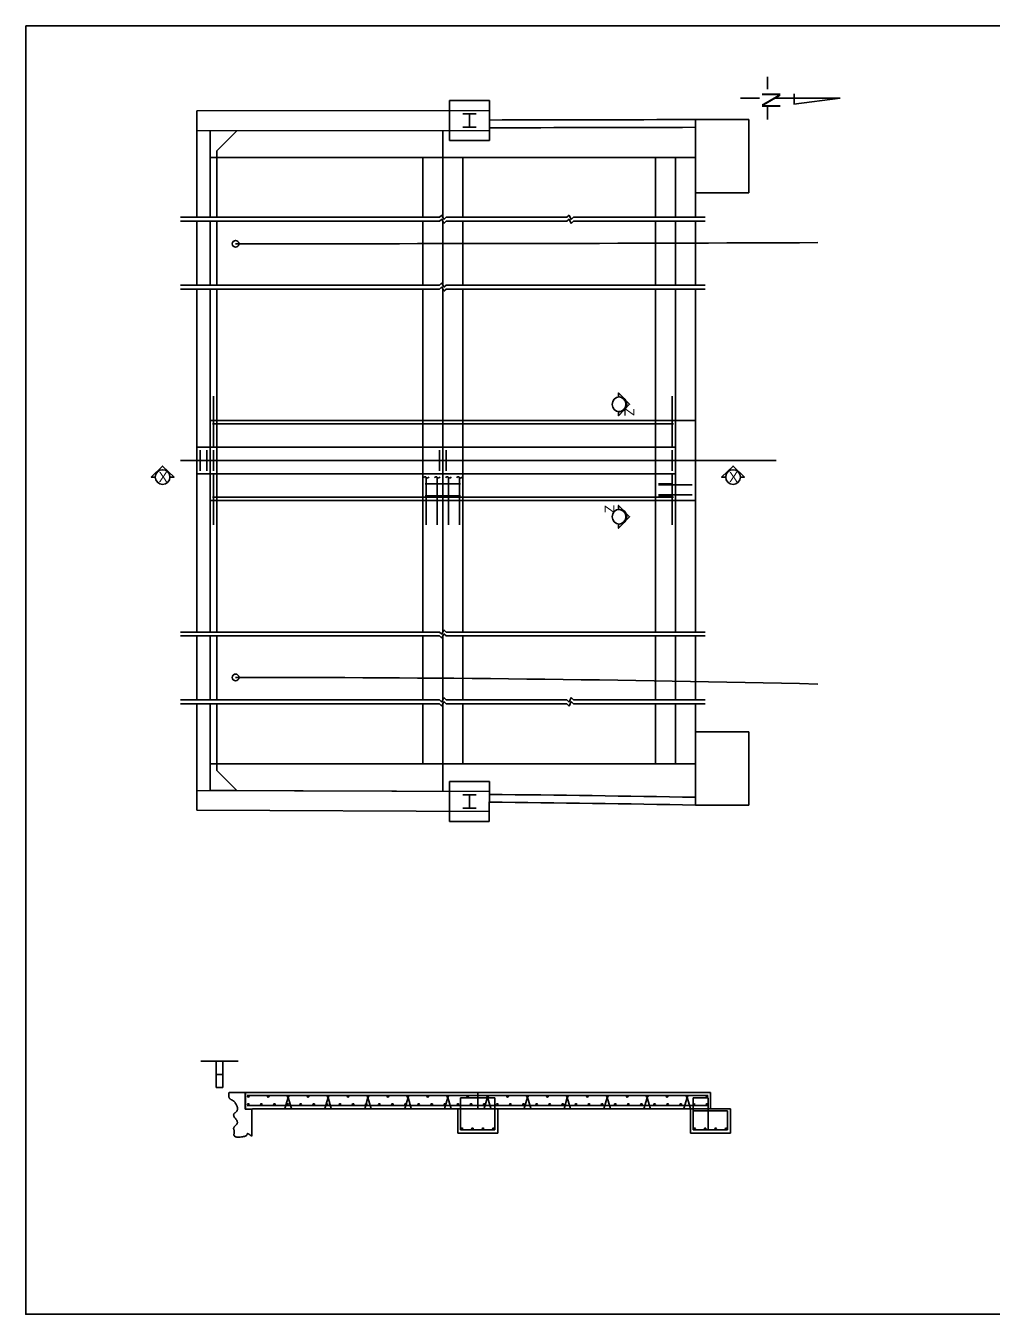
# Model space of a CAD drawing. Extents: x 1531 to 2925, y 1224 to 1658.
# Drawn here: x 2196.7 to 2269.3, y 1331.8 to 1428.7 of the extents above; entities that cross this region are included whole.
import ezdxf

# ---------------------------------------------------------------- set-up
doc = ezdxf.new("R2010")
doc.units = 0
for name, color, linetype in [('B_Border', 7, 'Continuous'), ('BD-EXIST-COSS', 7, 'Continuous'), ('BD-PROP-COSS', 7, 'Continuous'), ('BD-PROP-OSB', 7, 'Continuous'), ('D_FEMA A', 7, 'Continuous'), ('R_Border Prem', 7, 'Continuous'), ('R_Draft', 7, 'Continuous'), ('R_Guard Rail', 7, 'Continuous'), ('R_MOT', 7, 'Continuous'), ('R_Road Edge of Shoulder', 7, 'Continuous'), ('R_ROW Annot', 7, 'Continuous'), ('R_ROW_COA', 7, 'Continuous'), ('R_Survey Control', 7, 'Continuous'), ('R_Wall', 7, 'Continuous')]:
    doc.layers.add(name, color=color, linetype=linetype)

msp = doc.modelspace()

# ---------------------------------------------------------------- linework, layer by layer
at = {"layer": 'B_Border'}
msp.add_line((2208.361, 1396.032), (2253.154, 1396.032), dxfattribs=at)
at = {"layer": 'BD-EXIST-COSS'}
for p, q in [((2210.833, 1400.865), (2210.833, 1397.032)), ((2245.333, 1400.865), (2245.333, 1397.032)), ((2210.75, 1398.782), (2245.417, 1398.782)), ((2209.833, 1396.813), (2209.833, 1395.251)), ((2210.333, 1396.813), (2210.333, 1395.251)), ((2210.833, 1396.813), (2210.833, 1395.251)), ((2227.833, 1396.813), (2227.833, 1395.251)), ((2228.333, 1396.813), (2228.333, 1395.251)), ((2245.333, 1396.813), (2245.333, 1395.251)), ((2210.833, 1395.032), (2210.833, 1391.199)), ((2226.833, 1394.767), (2226.833, 1391.199)), ((2227.667, 1394.767), (2227.667, 1391.199)), ((2228.5, 1394.767), (2228.5, 1391.199)), ((2229.333, 1394.767), (2229.333, 1391.199)), ((2245.333, 1395.032), (2245.333, 1391.199)), ((2226.75, 1394.282), (2229.417, 1394.282)), ((2226.75, 1393.382), (2229.417, 1393.382)), ((2244.292, 1394.282), (2245.375, 1394.282)), ((2244.292, 1394.199), (2246.833, 1394.199)), ((2244.292, 1393.466), (2246.833, 1393.466)), ((2244.292, 1393.382), (2245.375, 1393.382)), ((2210.75, 1393.282), (2245.417, 1393.282)), ((2213.373, 1348.288), (2248.039, 1348.288)), ((2229.414, 1348.108), (2231.998, 1348.108)), ((2229.414, 1348.108), (2229.414, 1345.705)), ((2231.998, 1348.108), (2231.998, 1345.705)), ((2246.914, 1348.108), (2248.025, 1348.108)), ((2246.914, 1348.108), (2246.914, 1345.702)), ((2248.025, 1348.108), (2248.025, 1345.702)), ((2213.373, 1347.538), (2248.039, 1347.538)), ((2246.914, 1347.121), (2249.498, 1347.121)), ((2249.498, 1347.121), (2249.498, 1345.705)), ((2229.414, 1345.705), (2231.998, 1345.705)), ((2246.914, 1345.705), (2249.498, 1345.705))]:
    msp.add_line(p, q, dxfattribs=at)
for centre, radius in [((2213.449, 1348.225), 0.063), ((2214.949, 1348.225), 0.063), ((2216.449, 1348.225), 0.063), ((2217.949, 1348.225), 0.063), ((2219.449, 1348.225), 0.063), ((2220.949, 1348.225), 0.063), ((2222.449, 1348.225), 0.063), ((2223.949, 1348.225), 0.063), ((2225.449, 1348.225), 0.063), ((2226.949, 1348.225), 0.063), ((2228.449, 1348.225), 0.063), ((2229.949, 1348.225), 0.063), ((2231.449, 1348.225), 0.063), ((2232.949, 1348.225), 0.063), ((2234.449, 1348.225), 0.063), ((2235.949, 1348.225), 0.063), ((2237.449, 1348.225), 0.063), ((2238.949, 1348.225), 0.063), ((2240.449, 1348.225), 0.063), ((2241.949, 1348.225), 0.063), ((2243.449, 1348.225), 0.063), ((2244.949, 1348.225), 0.063), ((2246.449, 1348.225), 0.063), ((2247.949, 1348.225), 0.063), ((2213.449, 1347.601), 0.063), ((2214.435, 1347.601), 0.063), ((2215.421, 1347.601), 0.063), ((2216.406, 1347.601), 0.063), ((2217.392, 1347.601), 0.063), ((2218.378, 1347.601), 0.063), ((2219.363, 1347.601), 0.063), ((2220.349, 1347.601), 0.063), ((2221.335, 1347.601), 0.063), ((2222.321, 1347.601), 0.063), ((2223.306, 1347.601), 0.063), ((2224.292, 1347.601), 0.063), ((2225.278, 1347.601), 0.063), ((2226.263, 1347.601), 0.063), ((2227.249, 1347.601), 0.063), ((2228.235, 1347.601), 0.063), ((2229.22, 1347.601), 0.063), ((2230.206, 1347.601), 0.063), ((2231.192, 1347.601), 0.063), ((2232.178, 1347.601), 0.063), ((2233.163, 1347.601), 0.063), ((2234.149, 1347.601), 0.063), ((2235.135, 1347.601), 0.063), ((2236.12, 1347.601), 0.063), ((2237.106, 1347.601), 0.063), ((2238.092, 1347.601), 0.063), ((2239.078, 1347.601), 0.063), ((2240.063, 1347.601), 0.063), ((2241.049, 1347.601), 0.063), ((2242.035, 1347.601), 0.063), ((2243.02, 1347.601), 0.063), ((2244.006, 1347.601), 0.063), ((2244.992, 1347.601), 0.063), ((2245.978, 1347.601), 0.063), ((2246.963, 1347.601), 0.063), ((2247.949, 1347.601), 0.063), ((2229.522, 1345.77), 0.0625), ((2230.311, 1345.77), 0.0625), ((2231.101, 1345.77), 0.0625), ((2231.89, 1345.77), 0.0625), ((2247.022, 1345.77), 0.0625), ((2247.811, 1345.77), 0.0625), ((2248.601, 1345.77), 0.0625), ((2249.39, 1345.77), 0.0625)]:
    msp.add_circle(centre, radius, dxfattribs=at)
for centre, start, end in [((2226.741, 1394.713), 30.26081, 174.78761), ((2226.926, 1394.821), 210.26064, 354.78668), ((2227.574, 1394.713), 30.26081, 174.78761), ((2227.759, 1394.821), 210.26064, 354.78668), ((2228.407, 1394.713), 30.26081, 174.78761), ((2228.593, 1394.821), 210.26064, 354.78668), ((2229.241, 1394.713), 30.26081, 174.78761), ((2229.426, 1394.821), 210.26064, 354.78668)]:
    msp.add_arc(centre, 0.107, start, end, dxfattribs=at)
at = {"layer": 'BD-PROP-COSS'}
for p, q in [((2211.037, 1350.873), (2211.537, 1350.873)), ((2213.248, 1348.496), (2213.206, 1348.496)), ((2230.706, 1348.496), (2230.706, 1347.288))]:
    msp.add_line(p, q, dxfattribs=at)
at = {"layer": 'BD-PROP-OSB'}
for p, q in [((2211.037, 1349.873), (2211.037, 1350.873)), ((2211.037, 1350.873), (2211.537, 1350.873)), ((2211.537, 1350.873), (2211.537, 1350.873)), ((2211.537, 1350.873), (2211.537, 1349.873)), ((2211.537, 1349.873), (2211.037, 1349.873)), ((2211.037, 1348.894), (2211.037, 1349.873)), ((2211.037, 1349.873), (2211.537, 1349.873)), ((2211.537, 1349.873), (2211.537, 1349.873)), ((2211.537, 1349.873), (2211.537, 1348.894)), ((2211.537, 1348.894), (2211.037, 1348.894)), ((2213.206, 1348.496), (2213.206, 1348.496)), ((2213.206, 1348.496), (2213.206, 1348.413)), ((2213.248, 1348.496), (2213.206, 1348.496)), ((2213.206, 1348.413), (2213.206, 1348.413)), ((2213.206, 1348.413), (2213.248, 1348.413)), ((2213.248, 1348.413), (2213.206, 1348.413)), ((2213.206, 1348.413), (2213.206, 1348.413)), ((2213.206, 1348.413), (2213.206, 1347.246)), ((2213.248, 1348.413), (2213.248, 1348.496)), ((2213.248, 1347.246), (2213.248, 1348.413)), ((2213.206, 1347.246), (2213.248, 1347.246)), ((2213.206, 1347.246), (2213.206, 1347.246))]:
    msp.add_line(p, q, dxfattribs=at)
at = {"layer": 'D_FEMA A'}
for p, q in [((2216.212, 1347.3), (2216.455, 1348.144)), ((2216.455, 1348.144), (2216.698, 1347.3)), ((2219.206, 1347.292), (2219.449, 1348.137)), ((2219.449, 1348.137), (2219.692, 1347.292)), ((2222.207, 1347.288), (2222.45, 1348.132)), ((2222.45, 1348.132), (2222.693, 1347.288)), ((2225.22, 1347.294), (2225.464, 1348.138)), ((2225.464, 1348.138), (2225.707, 1347.294)), ((2228.214, 1347.278), (2228.457, 1348.123)), ((2228.457, 1348.123), (2228.7, 1347.278)), ((2231.199, 1347.302), (2231.442, 1348.146)), ((2231.442, 1348.146), (2231.685, 1347.302)), ((2234.207, 1347.304), (2234.45, 1348.149)), ((2234.45, 1348.149), (2234.693, 1347.304)), ((2237.197, 1347.283), (2237.44, 1348.128)), ((2237.44, 1348.128), (2237.683, 1347.283)), ((2240.201, 1347.285), (2240.444, 1348.13)), ((2240.444, 1348.13), (2240.687, 1347.285)), ((2243.207, 1347.275), (2243.45, 1348.119)), ((2243.45, 1348.119), (2243.694, 1347.275)), ((2246.211, 1347.295), (2246.454, 1348.14)), ((2246.454, 1348.14), (2246.697, 1347.295))]:
    msp.add_line(p, q, dxfattribs=at)
at = {"layer": 'R_Border Prem'}
for p, q in [((2231.583, 1420.849), (2210.583, 1420.834)), ((2210.583, 1420.834), (2210.583, 1418.833)), ((2228.083, 1420.847), (2228.083, 1418.833)), ((2210.583, 1418.833), (2247.083, 1418.833)), ((2247.083, 1399.032), (2210.583, 1399.032)), ((2210.583, 1399.032), (2210.583, 1397.032)), ((2226.583, 1399.032), (2226.583, 1393.032)), ((2228.083, 1399.032), (2228.083, 1393.032)), ((2229.583, 1393.032), (2229.583, 1399.032)), ((2244.083, 1399.032), (2244.083, 1393.032)), ((2245.583, 1399.032), (2245.583, 1393.032)), ((2247.083, 1399.032), (2247.083, 1393.032)), ((2210.583, 1397.032), (2210.583, 1395.032)), ((2210.583, 1395.032), (2210.583, 1393.032)), ((2247.083, 1393.032), (2210.583, 1393.032)), ((2210.583, 1373.231), (2247.083, 1373.231)), ((2228.083, 1371.217), (2228.083, 1373.231)), ((2210.583, 1371.226), (2231.583, 1371.135)), ((2212.702, 1350.873), (2211.537, 1350.873)), ((2211.537, 1350.873), (2211.537, 1348.894)), ((2213.248, 1348.496), (2248.206, 1348.496)), ((2213.248, 1348.496), (2213.248, 1347.246)), ((2248.206, 1348.496), (2248.206, 1347.288)), ((2213.248, 1347.246), (2213.706, 1347.246)), ((2213.706, 1347.246), (2213.789, 1347.288)), ((2213.789, 1347.288), (2249.706, 1347.288)), ((2229.206, 1347.288), (2229.206, 1345.455)), ((2232.206, 1347.288), (2232.206, 1345.455)), ((2246.706, 1347.288), (2246.706, 1345.455)), ((2249.706, 1347.288), (2249.706, 1345.455)), ((2229.206, 1345.455), (2232.206, 1345.455)), ((2246.706, 1345.455), (2249.706, 1345.455))]:
    msp.add_line(p, q, dxfattribs=at)
for points in [[(2251.083, 1421.677), (2247.083, 1421.677), (2247.083, 1416.177), (2251.083, 1416.177)], [(2251.083, 1375.624), (2247.083, 1375.624), (2247.083, 1370.124), (2251.083, 1370.124)]]:
    msp.add_lwpolyline(points, close=True, dxfattribs=at)
for centre, radius, start, end in [((2212.5, 12867.073), 11445.448, 270.0955282, 270.1731241), ((2212.5, 12866.489), 11445.448, 270.0955303, 270.1731241), ((2212.5, -525.92), 1896.359, 88.955056, 89.423525), ((2212.5, -525.337), 1896.359, 88.955591, 89.423449)]:
    msp.add_arc(centre, radius, start, end, dxfattribs=at)
at = {"layer": 'R_Draft'}
for p, q in [((2209.583, 1397.032), (2245.583, 1397.032)), ((2209.583, 1397.032), (2209.583, 1395.032)), ((2245.583, 1397.032), (2245.583, 1395.032)), ((2209.583, 1395.032), (2245.583, 1395.032))]:
    msp.add_line(p, q, dxfattribs=at)
at = {"layer": 'R_Guard Rail'}
for p, q in [((2228.582, 1423.097), (2231.582, 1423.099)), ((2228.582, 1423.097), (2228.582, 1422.347)), ((2231.582, 1423.099), (2231.582, 1422.349)), ((2231.582, 1422.349), (2209.583, 1422.333)), ((2209.583, 1414.326), (2209.583, 1422.333)), ((2228.582, 1422.347), (2228.583, 1420.847)), ((2229.582, 1422.098), (2230.582, 1422.099)), ((2230.083, 1421.098), (2230.082, 1422.098)), ((2231.583, 1420.849), (2231.582, 1422.349)), ((2231.583, 1420.849), (2209.583, 1420.833)), ((2210.583, 1414.326), (2210.583, 1420.833)), ((2212.583, 1420.833), (2211.083, 1419.333)), ((2228.583, 1420.847), (2228.584, 1420.097)), ((2229.583, 1421.098), (2230.583, 1421.099)), ((2231.583, 1420.849), (2231.584, 1420.099)), ((2228.584, 1420.097), (2231.584, 1420.099)), ((2210.583, 1416.626), (2210.583, 1418.833)), ((2210.583, 1418.833), (2210.583, 1414.326)), ((2211.083, 1414.326), (2211.083, 1419.333)), ((2226.583, 1418.833), (2226.583, 1414.326)), ((2228.083, 1418.833), (2228.083, 1414.326)), ((2229.583, 1418.833), (2229.583, 1414.326)), ((2244.083, 1414.326), (2244.083, 1418.833)), ((2245.583, 1414.326), (2245.583, 1418.833)), ((2247.083, 1414.326), (2247.083, 1418.833)), ((2209.583, 1414.026), (2209.583, 1409.226)), ((2210.583, 1414.026), (2210.583, 1409.226)), ((2210.583, 1414.026), (2210.583, 1409.226)), ((2211.083, 1414.026), (2211.083, 1409.226)), ((2226.583, 1414.026), (2226.583, 1409.226)), ((2228.083, 1414.026), (2228.083, 1409.226)), ((2229.583, 1414.026), (2229.583, 1409.226)), ((2244.083, 1414.026), (2244.083, 1409.226)), ((2245.583, 1414.026), (2245.583, 1409.226)), ((2247.083, 1414.026), (2247.083, 1409.226)), ((2209.583, 1408.926), (2209.583, 1383.138)), ((2210.583, 1408.926), (2210.583, 1399.032)), ((2211.083, 1408.926), (2211.083, 1383.138)), ((2226.583, 1408.926), (2226.583, 1399.032)), ((2228.083, 1408.96), (2228.083, 1399.032)), ((2229.583, 1408.926), (2229.583, 1399.032)), ((2244.083, 1408.926), (2244.083, 1399.032)), ((2245.583, 1408.926), (2245.583, 1399.032)), ((2247.083, 1408.926), (2247.083, 1399.032)), ((2210.583, 1403.526), (2210.583, 1383.138)), ((2210.583, 1399.032), (2210.583, 1393.032)), ((2210.583, 1393.032), (2210.583, 1383.138)), ((2226.583, 1383.138), (2226.583, 1393.032)), ((2228.083, 1383.138), (2228.083, 1393.032)), ((2229.583, 1383.138), (2229.583, 1393.032)), ((2244.083, 1393.032), (2244.083, 1383.138)), ((2245.583, 1393.032), (2245.583, 1383.138)), ((2247.083, 1393.032), (2247.083, 1383.138)), ((2209.583, 1378.038), (2209.583, 1382.838)), ((2210.583, 1378.038), (2210.583, 1382.838)), ((2210.583, 1378.038), (2210.583, 1382.838)), ((2211.083, 1378.038), (2211.083, 1382.838)), ((2226.583, 1378.038), (2226.583, 1382.838)), ((2228.083, 1377.988), (2228.083, 1382.838)), ((2229.583, 1378.038), (2229.583, 1382.838)), ((2244.083, 1378.038), (2244.083, 1382.838)), ((2245.583, 1378.038), (2245.583, 1382.838)), ((2247.083, 1378.038), (2247.083, 1382.838)), ((2209.583, 1377.738), (2209.583, 1369.731)), ((2210.583, 1377.738), (2210.583, 1373.231)), ((2210.583, 1377.738), (2210.583, 1371.231)), ((2211.083, 1377.738), (2211.083, 1372.731)), ((2226.583, 1373.231), (2226.583, 1377.738)), ((2228.083, 1373.231), (2228.083, 1377.738)), ((2229.583, 1373.231), (2229.583, 1377.738)), ((2244.083, 1377.738), (2244.083, 1373.231)), ((2245.583, 1377.738), (2245.583, 1373.231)), ((2247.083, 1377.738), (2247.083, 1373.231)), ((2212.583, 1371.231), (2211.083, 1372.731)), ((2209.583, 1371.231), (2231.583, 1371.135)), ((2228.577, 1369.648), (2228.583, 1371.148)), ((2228.583, 1371.148), (2228.586, 1371.898)), ((2228.586, 1371.898), (2231.586, 1371.885)), ((2231.577, 1369.635), (2231.583, 1371.135)), ((2231.583, 1371.135), (2231.586, 1371.885)), ((2229.582, 1370.893), (2230.582, 1370.889)), ((2230.082, 1370.891), (2230.078, 1369.891)), ((2209.583, 1369.731), (2231.577, 1369.635)), ((2228.573, 1368.898), (2228.577, 1369.648)), ((2229.578, 1369.893), (2230.578, 1369.889)), ((2231.573, 1368.885), (2231.577, 1369.635)), ((2228.573, 1368.898), (2231.573, 1368.885))]:
    msp.add_line(p, q, dxfattribs=at)
at = {"layer": 'R_MOT'}
for p, q in [((2252.508, 1424.884), (2252.508, 1423.958)), ((2254.5, 1423.617), (2254.5, 1422.841)), ((2250.465, 1423.279), (2251.901, 1423.279)), ((2252.508, 1422.662), (2252.508, 1421.673)), ((2253.084, 1423.279), (2257.965, 1423.279)), ((2257.965, 1423.279), (2254.474, 1422.842))]:
    msp.add_line(p, q, dxfattribs=at)
at = {"layer": 'R_Road Edge of Shoulder'}
for p, q in [((2209.873, 1350.873), (2211.037, 1350.873)), ((2211.037, 1350.873), (2211.037, 1348.894)), ((2213.206, 1348.496), (2212.007, 1348.496)), ((2213.706, 1345.216), (2213.706, 1347.246))]:
    msp.add_line(p, q, dxfattribs=at)
msp.add_open_spline([(2213.706, 1345.216), (2213.366, 1345.517), (2213.354, 1345.208), (2212.347, 1345.095), (2212.403, 1345.671), (2212.302, 1345.861), (2212.754, 1346.263), (2212.221, 1346.825), (2212.725, 1347.171), (2212.459, 1347.846), (2211.903, 1348.078), (2212.007, 1348.496)], degree=2, dxfattribs=at)
at = {"layer": 'R_ROW Annot'}
for p, q in [((2231.583, 1420.849), (2231.583, 1421.641)), ((2247.083, 1418.833), (2247.083, 1421.677)), ((2210.583, 1373.231), (2210.583, 1371.226)), ((2247.083, 1373.231), (2247.083, 1370.124)), ((2210.583, 1371.226), (2212.5, 1371.218)), ((2231.583, 1371.135), (2231.58, 1370.343))]:
    msp.add_line(p, q, dxfattribs=at)
at = {"layer": 'R_ROW_COA'}
for centre, radius, start, end in [((2212.5, 12871.49), 11459.156, 270.0000001, 270.2189058), ((2212.5, -530.133), 1909.859, 88.686453, 90)]:
    msp.add_arc(centre, radius, start, end, dxfattribs=at)
at = {"layer": 'R_Survey Control'}
for points in [[(2241.3, 1400.814), (2241.3, 1401.121), (2242.127, 1400.262), (2241.3, 1399.402), (2241.3, 1399.709)], [(2206.454, 1394.788), (2206.147, 1394.788), (2207.007, 1395.615), (2207.866, 1394.788), (2207.559, 1394.788)], [(2249.354, 1394.788), (2249.046, 1394.788), (2249.906, 1395.615), (2250.766, 1394.788), (2250.459, 1394.788)], [(2241.3, 1391.25), (2241.3, 1390.943), (2242.127, 1391.802), (2241.3, 1392.662), (2241.3, 1392.355)]]:
    msp.add_lwpolyline(points, dxfattribs=at)
for centre in [(2241.367, 1400.259), (2207.009, 1394.788), (2249.906, 1394.788), (2241.367, 1391.805)]:
    msp.add_circle(centre, 0.552, dxfattribs=at)
for centre, start, end in [((2241.3, 1400.262), 270, 90), ((2207.007, 1394.788), 0, 180), ((2249.906, 1394.788), 0, 180), ((2241.3, 1391.802), 270, 90)]:
    msp.add_arc(centre, 0.552, start, end, dxfattribs=at)
at = {"layer": 'R_Wall'}
for p, q in [((2208.361, 1414.326), (2227.833, 1414.326)), ((2208.361, 1414.026), (2227.833, 1414.026)), ((2227.833, 1414.326), (2228, 1414.493)), ((2227.833, 1414.026), (2228, 1414.193)), ((2228, 1414.493), (2228.167, 1414.16)), ((2228, 1414.193), (2228.167, 1413.86)), ((2228.167, 1414.16), (2228.333, 1414.326)), ((2228.167, 1413.86), (2228.333, 1414.026)), ((2228.333, 1414.326), (2237.409, 1414.326)), ((2228.333, 1414.026), (2237.409, 1414.026)), ((2237.409, 1414.326), (2237.576, 1414.493)), ((2237.409, 1414.026), (2237.576, 1414.193)), ((2237.576, 1414.493), (2237.743, 1414.16)), ((2237.576, 1414.193), (2237.743, 1413.86)), ((2237.743, 1414.16), (2237.909, 1414.326)), ((2237.743, 1413.86), (2237.909, 1414.026)), ((2237.909, 1414.326), (2247.806, 1414.326)), ((2237.909, 1414.026), (2247.806, 1414.026)), ((2208.361, 1409.226), (2227.833, 1409.226)), ((2208.361, 1408.926), (2227.833, 1408.926)), ((2227.833, 1409.226), (2228, 1409.393)), ((2227.833, 1408.926), (2228, 1409.093)), ((2228, 1409.393), (2228.167, 1409.06)), ((2228, 1409.093), (2228.167, 1408.76)), ((2228.167, 1409.06), (2228.333, 1409.226)), ((2228.167, 1408.76), (2228.333, 1408.926)), ((2228.333, 1409.226), (2247.806, 1409.226)), ((2228.333, 1408.926), (2247.806, 1408.926)), ((2208.361, 1383.138), (2227.833, 1383.138)), ((2208.361, 1382.838), (2227.833, 1382.838)), ((2227.833, 1383.138), (2228, 1382.971)), ((2227.833, 1382.838), (2228, 1382.671)), ((2228, 1382.971), (2228.167, 1383.304)), ((2228, 1382.671), (2228.167, 1383.004)), ((2228.167, 1383.304), (2228.333, 1383.138)), ((2228.167, 1383.004), (2228.333, 1382.838)), ((2228.333, 1383.138), (2247.806, 1383.138)), ((2228.333, 1382.838), (2247.806, 1382.838)), ((2208.361, 1378.038), (2227.833, 1378.038)), ((2227.833, 1378.038), (2228, 1377.871)), ((2228, 1377.871), (2228.167, 1378.204)), ((2228, 1377.571), (2228.167, 1377.904)), ((2228.167, 1378.204), (2228.333, 1378.038)), ((2228.167, 1377.904), (2228.333, 1377.738)), ((2228.333, 1378.038), (2237.409, 1378.038)), ((2237.409, 1378.038), (2237.576, 1377.871)), ((2237.576, 1377.871), (2237.743, 1378.204)), ((2237.576, 1377.571), (2237.743, 1377.904)), ((2237.743, 1378.204), (2237.909, 1378.038)), ((2237.743, 1377.904), (2237.909, 1377.738)), ((2237.909, 1378.038), (2247.806, 1378.038)), ((2208.361, 1377.738), (2227.833, 1377.738)), ((2227.833, 1377.738), (2228, 1377.571)), ((2228.333, 1377.738), (2237.409, 1377.738)), ((2237.409, 1377.738), (2237.576, 1377.571)), ((2237.909, 1377.738), (2247.806, 1377.738))]:
    msp.add_line(p, q, dxfattribs=at)
msp.add_lwpolyline([(2196.716, 1428.728), (2341.933, 1428.728), (2341.933, 1331.833), (2196.716, 1331.833)], close=True, dxfattribs=at)
for centre in [(2212.5, 1412.334), (2212.5, 1379.726)]:
    msp.add_circle(centre, 0.25, dxfattribs=at)

# ---------------------------------------------------------------- texts
at = {"layer": 'R_MOT'}
msp.add_text('N', height=1.396, rotation=270, dxfattribs=at).set_placement((2252.078, 1423.808))
at = {"layer": 'R_Survey Control'}
for s, rotation, p in [('Z', 270, (2241.742, 1399.987)), ('X', 360, (2206.712, 1394.413)), ('X', 360, (2249.609, 1394.413)), ('Z', 90, (2240.992, 1392.077))]:
    msp.add_text(s, height=0.75, rotation=rotation, dxfattribs=at).set_placement(p)

doc.saveas('drawing.dxf')
